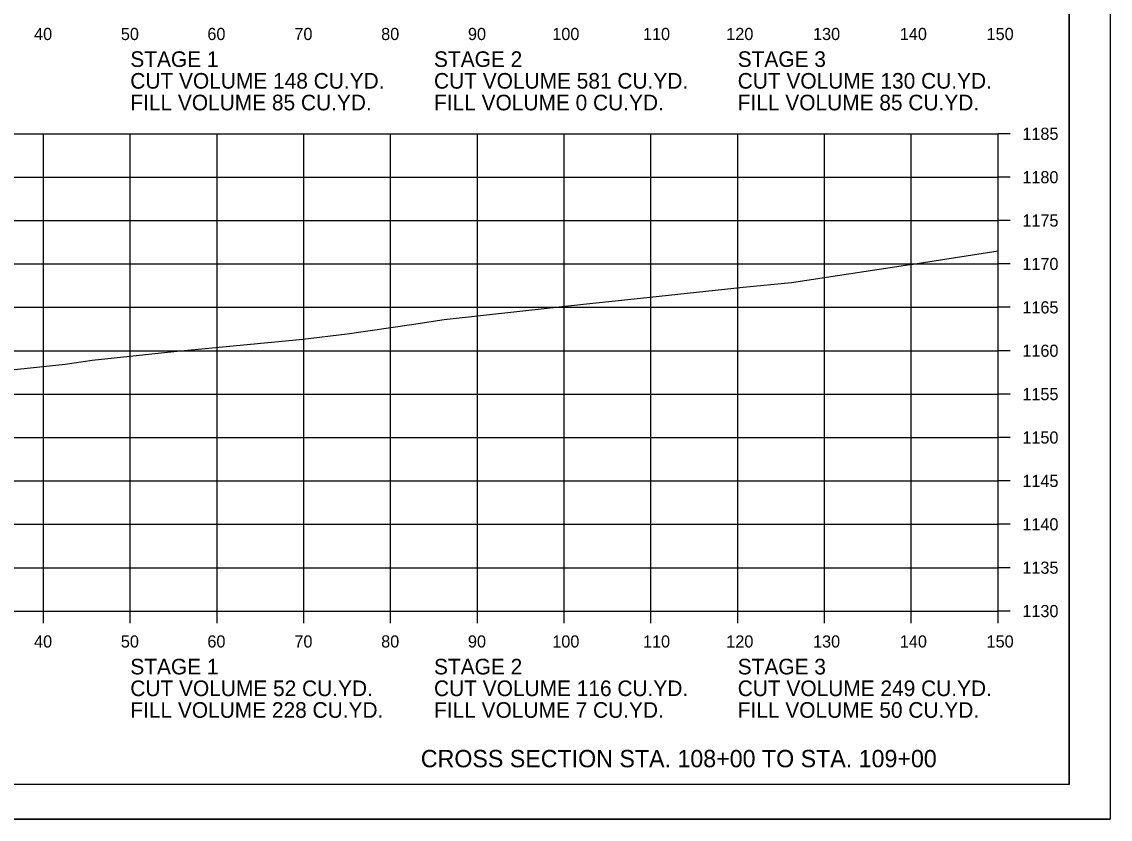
# Model space of a CAD drawing. Extents: x 1368971 to 1374497, y 378717 to 381839.
# Drawn here: x 1371090.2 to 1371215.6, y 379357.1 to 379449 of the extents above; entities that cross this region are included whole.
import ezdxf

# ---------------------------------------------------------------- set-up
doc = ezdxf.new("R2010")
doc.units = 0
for name, color, linetype in [('R_Axis', 7, 'Continuous'), ('R_Axis Annot', 7, 'Continuous'), ('R_Border', 7, 'Continuous'), ('R_Draft', 7, 'Continuous'), ('R_Exist Surface', 7, 'Continuous'), ('R_Grid', 7, 'Continuous'), ('R_No Plot', 7, 'Continuous')]:
    doc.layers.add(name, color=color, linetype=linetype)

msp = doc.modelspace()

# ---------------------------------------------------------------- linework, layer by layer
at = {"layer": 'R_Axis'}
for p, q in [((1371202.71, 379381.08), (1371202.71, 379436.08)), ((1371204.11, 379436.08), (1371202.71, 379436.08)), ((1371204.11, 379431.08), (1371202.71, 379431.08)), ((1371204.11, 379426.08), (1371202.71, 379426.08)), ((1371204.11, 379421.08), (1371202.71, 379421.08)), ((1371204.11, 379416.08), (1371202.71, 379416.08)), ((1371204.11, 379411.08), (1371202.71, 379411.08)), ((1371204.11, 379406.08), (1371202.71, 379406.08)), ((1371204.11, 379401.08), (1371202.71, 379401.08)), ((1371204.11, 379396.08), (1371202.71, 379396.08)), ((1371204.11, 379391.08), (1371202.71, 379391.08)), ((1371204.11, 379386.08), (1371202.71, 379386.08)), ((1370902.71, 379381.08), (1371202.71, 379381.08)), ((1371092.71, 379379.68), (1371092.71, 379381.08)), ((1371102.71, 379379.68), (1371102.71, 379381.08)), ((1371112.71, 379379.68), (1371112.71, 379381.08)), ((1371122.71, 379379.68), (1371122.71, 379381.08)), ((1371132.71, 379379.68), (1371132.71, 379381.08)), ((1371142.71, 379379.68), (1371142.71, 379381.08)), ((1371152.71, 379379.68), (1371152.71, 379381.08)), ((1371162.71, 379379.68), (1371162.71, 379381.08)), ((1371172.71, 379379.68), (1371172.71, 379381.08)), ((1371182.71, 379379.68), (1371182.71, 379381.08)), ((1371192.71, 379379.68), (1371192.71, 379381.08)), ((1371202.71, 379379.68), (1371202.71, 379381.08)), ((1371204.11, 379381.08), (1371202.71, 379381.08))]:
    msp.add_line(p, q, dxfattribs=at)
at = {"layer": 'R_Border'}
for q in [(1371210.89, 379566.54), (1370894.71, 379361.08)]:
    msp.add_line((1371210.89, 379361.08), q, dxfattribs=at)
at = {"layer": 'R_Exist Surface'}
msp.add_lwpolyline([(1371080.23, 379408), (1371090.47, 379409.04), (1371095.19, 379409.53), (1371098.3, 379409.98), (1371107.72, 379411), (1371122.6, 379412.41), (1371127.72, 379413.04), (1371135.12, 379414.09), (1371138.87, 379414.67), (1371143.42, 379415.16), (1371154.93, 379416.43), (1371162.57, 379417.27), (1371173.33, 379418.4), (1371178.92, 379418.94), (1371192.54, 379421.01), (1371192.94, 379421.05), (1371194.11, 379421.25), (1371202.71, 379422.58)], dxfattribs=at)
at = {"layer": 'R_Grid'}
for p, q in [((1370902.71, 379436.08), (1371202.71, 379436.08)), ((1371092.71, 379381.08), (1371092.71, 379436.08)), ((1371102.71, 379381.08), (1371102.71, 379436.08)), ((1371112.71, 379381.08), (1371112.71, 379436.08)), ((1371122.71, 379381.08), (1371122.71, 379436.08)), ((1371132.71, 379381.08), (1371132.71, 379436.08)), ((1371142.71, 379381.08), (1371142.71, 379436.08)), ((1371152.71, 379381.08), (1371152.71, 379436.08)), ((1371162.71, 379381.08), (1371162.71, 379436.08)), ((1371172.71, 379381.08), (1371172.71, 379436.08)), ((1371182.71, 379381.08), (1371182.71, 379436.08)), ((1371192.71, 379381.08), (1371192.71, 379436.08)), ((1371202.71, 379381.08), (1371202.71, 379436.08)), ((1370902.71, 379431.08), (1371202.71, 379431.08)), ((1370902.71, 379426.08), (1371202.71, 379426.08)), ((1370902.71, 379421.08), (1371202.71, 379421.08)), ((1370902.71, 379416.08), (1371202.71, 379416.08)), ((1370902.71, 379411.08), (1371202.71, 379411.08)), ((1370902.71, 379406.08), (1371202.71, 379406.08)), ((1370902.71, 379401.08), (1371202.71, 379401.08)), ((1370902.71, 379396.08), (1371202.71, 379396.08)), ((1370902.71, 379391.08), (1371202.71, 379391.08)), ((1370902.71, 379386.08), (1371202.71, 379386.08)), ((1370902.71, 379381.08), (1371202.71, 379381.08))]:
    msp.add_line(p, q, dxfattribs=at)
at = {"layer": 'R_No Plot'}
msp.add_line((1370882.31, 379357.1), (1371215.64, 379357.1), dxfattribs=at)
for points in [[(1370882.3, 379570.43), (1371215.64, 379570.43), (1371215.64, 379357.09), (1370882.3, 379357.09)], [(1371128.63, 379566.54), (1371128.63, 379556.66), (1371164.36, 379556.66), (1371164.36, 379553.74), (1371187.56, 379553.74), (1371187.56, 379529.4), (1371210.89, 379529.4), (1371210.89, 379361.08), (1370894.71, 379361.08), (1370894.71, 379566.54)]]:
    msp.add_lwpolyline(points, close=True, dxfattribs=at)

# ---------------------------------------------------------------- texts
at = {"layer": 'R_Axis Annot'}
for s, height, p in [('40', 1.4, (1371091.62, 379446.88)), ('50', 1.4, (1371101.62, 379446.88)), ('60', 1.4, (1371111.59, 379446.88)), ('70', 1.4, (1371121.62, 379446.88)), ('80', 1.4, (1371131.62, 379446.88)), ('90', 1.4, (1371141.62, 379446.88)), ('100', 1.4, (1371151.34, 379446.88)), ('110', 1.4, (1371161.79, 379446.88)), ('120', 1.4, (1371171.39, 379446.88)), ('130', 1.4, (1371181.39, 379446.88)), ('140', 1.4, (1371191.39, 379446.88)), ('150', 1.4, (1371201.39, 379446.88)), ('STAGE 1', 1.8, (1371102.71, 379443.78)), ('STAGE 2', 1.8, (1371137.71, 379443.78)), ('STAGE 3', 1.8, (1371172.71, 379443.78)), ('CUT VOLUME 148 CU.YD.', 1.8, (1371102.71, 379441.28)), ('CUT VOLUME 581 CU.YD.', 1.8, (1371137.71, 379441.28)), ('CUT VOLUME 130 CU.YD.', 1.8, (1371172.71, 379441.28)), ('FILL VOLUME 85 CU.YD.', 1.8, (1371102.71, 379438.78)), ('FILL VOLUME 0 CU.YD.', 1.8, (1371137.71, 379438.78)), ('FILL VOLUME 85 CU.YD.', 1.8, (1371172.71, 379438.78)), ('1185', 1.4, (1371205.51, 379435.38)), ('1180', 1.4, (1371205.51, 379430.38)), ('1175', 1.4, (1371205.51, 379425.38)), ('1170', 1.4, (1371205.51, 379420.38)), ('1165', 1.4, (1371205.51, 379415.38)), ('1160', 1.4, (1371205.51, 379410.38)), ('1155', 1.4, (1371205.51, 379405.38)), ('1150', 1.4, (1371205.51, 379400.38)), ('1145', 1.4, (1371205.51, 379395.38)), ('1140', 1.4, (1371205.51, 379390.38)), ('1135', 1.4, (1371205.51, 379385.38)), ('1130', 1.4, (1371205.51, 379380.38)), ('40', 1.4, (1371091.62, 379376.88)), ('50', 1.4, (1371101.62, 379376.88)), ('60', 1.4, (1371111.59, 379376.88)), ('70', 1.4, (1371121.62, 379376.88)), ('80', 1.4, (1371131.62, 379376.88)), ('90', 1.4, (1371141.62, 379376.88)), ('100', 1.4, (1371151.34, 379376.88)), ('110', 1.4, (1371161.79, 379376.88)), ('120', 1.4, (1371171.39, 379376.88)), ('130', 1.4, (1371181.39, 379376.88)), ('140', 1.4, (1371191.39, 379376.88)), ('150', 1.4, (1371201.39, 379376.88)), ('STAGE 1', 1.8, (1371102.71, 379373.78)), ('STAGE 2', 1.8, (1371137.71, 379373.78)), ('STAGE 3', 1.8, (1371172.71, 379373.78)), ('CUT VOLUME 52 CU.YD.', 1.8, (1371102.71, 379371.28)), ('CUT VOLUME 116 CU.YD.', 1.8, (1371137.71, 379371.28)), ('CUT VOLUME 249 CU.YD.', 1.8, (1371172.71, 379371.28)), ('FILL VOLUME 228 CU.YD.', 1.8, (1371102.71, 379368.78)), ('FILL VOLUME 7 CU.YD.', 1.8, (1371137.71, 379368.78)), ('FILL VOLUME 50 CU.YD.', 1.8, (1371172.71, 379368.78))]:
    msp.add_text(s, height=height, dxfattribs=at).set_placement(p)
at = {"layer": 'R_Draft'}
msp.add_text('CROSS SECTION STA. 108+00 TO STA. 109+00', height=2, dxfattribs=at).set_placement((1371136.19, 379363.08))

doc.saveas('drawing.dxf')
